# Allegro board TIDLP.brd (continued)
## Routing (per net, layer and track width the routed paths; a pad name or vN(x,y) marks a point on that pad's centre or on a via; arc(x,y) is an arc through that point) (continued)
UART1_DTR_CON: length 3.2
  TOP w0.178: R22.1 197.62,70.98 J21.4
UART1_RSTZ_CON: length 8.2
  TOP w0.178: U12.14 191.09,71.34 191.43,71.67 192.68,71.67 193.11,72.1 193.11,72.1 193.91,72.9 195.71,72.9 196.22,72.39 197.65,72.39 J21.8
UART1_RTSZ: length 121.1
  TOP w0.178: v1(136.68,72.47) 137.51,72.47 137.56,72.52 140.55,72.52 140.91,72.16 v1(141.59,72.16) ; U11.A19 v2(80.66,82.2) ; U12.11 189.14,69.01 v1(188.98,68.85)
  LY4 w0.102: 107.45,73.16 107.02,73.59 99.36,73.59 98.55,74.4 98.42,74.4 96.78,76.04 90,76.04 87.46,78.58 87.46,78.82 87.09,79.19 87.09,79.73 86.03,80.8 85.51,80.8 85.27,81.04 85.27,81.15 84.83,81.59 84.5,81.59 84.27,81.36 84.27,80.76 84.1,80.59 83.19,80.59 83.06,80.73 83.06,81.36 82.83,81.59 82.23,81.59 82.02,81.81 81.5,81.81 81.11,82.2 v2(80.66,82.2)
  LY4 w0.171: 107.45,73.16 111.26,73.16 111.49,72.93 114,72.93 114.23,73.16 117.44,73.16 118.47,72.13 132.56,72.13 133.36,72.92 135.63,72.92 136.08,72.47 v1(136.68,72.47) ; v1(188.98,68.85) 187.95,67.82 177.02,67.82 174.57,70.27 171.22,70.27 170.92,69.98 167.23,69.98 166.93,70.27 166.06,70.27 164.89,71.44 161.2,71.44 160.95,71.69 160.03,71.69 159.78,71.44 158.78,71.44 158.09,72.13 156.86,72.13 156.31,72.68 154.13,72.68 153.58,72.13 141.62,72.13 v1(141.59,72.16)
UART1_RXD: length 243.5
  TOP w0.178: U12.9 186.55,70.57 v1(185.82,69.84) ; v1(141.83,73.86) 137.98,73.86 137.93,73.91 137.4,73.91 137.2,73.7 v1(136.63,73.7) ; v1(114.99,110.07) 114.99,111.23 115.1,111.34 115.1,111.85 114.99,111.96 114.99,112.12 114.88,112.23 114.88,112.73 114.99,112.84 J3.92 ; U11.D19 v2(83.66,82.2)
  LY3 w0.171: v1(134.76,108.69) 129.76,108.69 v1(129.6,108.54) ; v1(189.19,107.49) 187.62,105.92 186.63,105.92 185.86,105.14 185.86,104.03 186.24,103.65 186.5,103.65 188.37,101.78 188.37,99.61 185.87,97.11 185.87,89.86 184.28,88.27 184.28,86.45 185.29,85.44 185.29,82.02 184.94,81.67 184.94,81.17 185.72,80.39 185.72,75.71 186.05,75.38 186.05,74.49 184.93,73.37 184.93,70.74 v1(185.82,69.84)
  LY4 w0.102: v2(83.66,82.2) 84.11,82.2 84.5,82.59 84.83,82.59 85.06,82.36 85.06,82 85.26,81.8 85.91,81.8 87.87,79.84 87.87,78.85 90.17,76.55 96.85,76.55 98.59,74.81 99.02,74.81 99.23,74.59 106.88,74.59 107.45,74.03
  LY4 w0.171: v1(141.83,73.86) 142.89,73.86 143.69,73.06 153.29,73.06 153.91,73.68 156.53,73.68 156.97,73.24 161.18,73.24 162.11,72.31 166,72.31 166.78,71.53 170.18,71.53 170.25,71.6 175.99,71.6 177.09,70.51 177.09,70.48 178.43,69.14 178.92,69.14 179.34,69.56 180.53,69.56 181.33,68.76 184.26,68.76 185.35,69.84 v1(185.82,69.84) ; v1(136.63,73.7) 136.57,73.63 133.06,73.63 132.49,73.06 119.51,73.06 118.55,74.03 114.09,74.03 113.7,73.65 111.78,73.65 111.4,74.03 107.45,74.03 ; v1(189.19,107.49) 187.75,108.93 178.53,108.93 176.75,107.15 175.87,107.15 173.74,105.02 173.03,104.31 173.03,104.31 172.03,103.31 166.8,103.31 165.95,104.16 165.1,104.16 165.02,104.08 163.6,104.08 163.14,103.62 156.24,103.62 155.21,104.65 138.73,104.65 134.76,108.62 v1(134.76,108.69)
  BOTTOM w0.178: v1(114.99,110.07) 115.89,110.07 116.84,109.12 118.14,109.12 118.35,108.91 126.21,108.91 126.84,108.28 128.22,108.28 128.29,108.21 129.27,108.21 v1(129.6,108.54)
UART1_RXD_CON: length 13
  TOP w0.178: v1(186.82,76.07) 187.24,76.49 U12.8 ; v1(195.14,73.98) 195.33,73.79 J21.3
  BOTTOM w0.178: v1(195.14,73.98) 195.14,73.98 193.62,75.5 187.39,75.5 v1(186.82,76.07)
UART1_TXD: length 273.1
  TOP w0.178: J3.53 100.49,120.98 100.55,121.05 100.55,121.93 100.49,122 v1(100.49,122.27) ; v1(142.26,80.65) 142.02,80.41 141.88,80.41 139.75,78.28 129.93,78.28 128.85,77.19 127.75,77.19 125.91,75.35 123.58,75.35 123.27,75.65 123.27,76.15 122.51,76.92 122.45,76.92 122.27,77.1 122.27,84.11 125.35,87.19 125.7,87.19 126.04,87.54 126.04,87.91 127.62,89.49 127.62,89.97 134.77,97.11 136.41,97.11 138.16,98.86 138.16,104.56 138.11,104.6 138.11,104.94 137.48,105.57 137.48,105.68 137.11,106.05 137,106.05 135.57,107.48 135.57,109.86 134.3,111.12 134.3,112.72 136.12,114.54 136.12,118.87 140.09,122.84 141.84,122.84 v1(146.49,127.5) ; v1(186.75,69.85) 187.15,69.85 187.53,69.47 188.16,69.47 188.36,69.67 188.36,70.44 U12.10 ; v1(137.67,73.27) 137.83,73.1 v1(140.87,73.1) ; U11.C19 v2(82.66,82.2)
  LY4 w0.102: v2(82.66,82.2) 83.27,81.59 84.21,81.59 84.42,81.8 84.91,81.8 85.11,81.59 85.83,81.59 86.06,81.36 86.06,81.35 86.23,81.18 86.23,80.98 87.66,79.55 87.66,78.77 90.12,76.31 96.8,76.31 98.51,74.6 98.77,74.6 99.57,73.8 107.12,73.8 107.33,73.6 107.63,73.6
  LY4 w0.171: v1(137.67,73.27) 137.46,73.06 136.94,73.06 136.93,73.07 135.99,73.07 135.78,73.28 133.21,73.28 132.54,72.61 118.83,72.61 117.84,73.6 114.16,73.6 113.85,73.29 111.64,73.29 111.33,73.6 107.63,73.6 ; v1(186.75,69.85) 185.15,68.25 177.73,68.25 175.28,70.7 171.04,70.7 170.74,70.41 167.41,70.41 167.11,70.7 166.26,70.7 166.26,70.7 166.24,70.7 165.07,71.87 161.38,71.87 161.13,72.12 160.55,72.12 160.07,72.61 156.99,72.61 156.43,73.17 154.01,73.17 153.45,72.61 141.99,72.61 141.84,72.76 141.22,72.76 v1(140.87,73.1)
  BOTTOM w0.178: v1(142.26,80.65) 142.28,80.64 142.28,77.87 v1(137.67,73.27) ; v1(100.49,122.27) 100.49,123.19 102.28,124.99 107.3,124.99 108.84,123.44 110.91,123.44 112.61,121.74 112.61,120.51 113.83,119.29 115.18,119.29 115.18,119.29 115.8,119.29 115.8,119.29 116.84,119.29 117.01,119.28 120.22,119.28 122.23,117.28 124.25,117.28 124.75,117.77 125.77,117.77 126.63,118.63 127.73,118.63 130.62,121.52 130.62,121.79 132.97,124.13 136.74,124.13 137.71,125.1 139.5,125.1 139.5,125.09 143.61,125.09 146.02,127.5 v1(146.49,127.5)
UART1_TXD_CON: length 11.4
  TOP w0.178: J21.2 197.55,76.45 194.25,76.45 193.71,75.92 193.24,75.92 192,74.68 189.09,74.68 188.49,75.27 U12.7
USB_DAT_N: length 14.5
  LY4 w0.105: J5.2 7.35,109.45 7.35,110.28 8.36,111.29 12.28,111.29 12.68,111.69 12.68,112.34 12.81,112.47 v1(14.51,112.47)
  BOTTOM w0.108: U503.4 13.53,112.47 v1(14.51,112.47) 14.51,112.77 14.88,113.14 16.25,113.14 16.51,112.88 R515.1
USB_DAT_NS: length 150.7
  TOP w0.178: U11.C5 v2(82.66,67.2)
  LY4 w0.102: v2(82.66,67.2) 82.66,67.04 82.85,66.85 83.06,66.85 83.14,66.94 83.14,67.46 83,67.6 81.51,67.6 81.27,67.36 81.27,65.96 80.91,65.6 80.15,65.6 79.82,65.27 79.82,64.68 78.8,63.66 78.76,63.66
  LY4 w0.105: v1(16.57,118.61) 16.58,118.61 16.93,118.25 16.93,115.18 16.03,114.28 16.03,111.08 8.02,103.06 8.02,87.18 8.58,86.62 8.58,86.11 9.22,85.47 9.22,71.1 15.05,65.26 24.57,65.26 32.75,57.07 45.27,57.07 46.57,55.77 57.29,55.77 58.37,54.69 61.54,54.69 63.06,56.21 63.76,56.21 65.8,58.25 72.96,58.25 76.16,61.46 76.16,62.2 77.62,63.66 78.76,63.66
  BOTTOM w0.108: v1(16.57,118.61) 16.14,119.03 12.86,119.03 12.65,118.82 12.65,118.21 12.89,118.11 DN504.1 13.88,118.11 15.1,116.89 R515.2
USB_DAT_P: length 15.5
  LY4 w0.105: J5.3 7.1,109.39 7.1,110.39 8.26,111.55 12.18,111.55 12.42,111.79 12.42,112.34 12.29,112.47 v1(10.59,112.47)
  BOTTOM w0.108: R516.1 v1(10.59,112.47) 11.62,112.47 U503.6 11.62,110.58 R539.1
USB_DAT_PS: length 150.7
  TOP w0.178: U11.D6 v2(83.66,68.2)
  LY4 w0.102: 78.76,63.91 78.76,63.91 79.61,64.76 79.61,65.35 80.07,65.81 80.83,65.81 81.06,66.04 81.06,66.06 81.07,66.07 81.07,67.45 81.42,67.81 83.27,67.81 v2(83.66,68.2)
  LY4 w0.105: v1(17.56,118.61) 17.19,118.23 17.19,115.07 16.29,114.17 16.29,110.97 8.27,102.95 8.27,87.29 8.83,86.73 8.83,86.21 9.47,85.57 9.47,71.2 15.16,65.51 24.67,65.51 32.86,57.33 45.37,57.33 46.68,56.02 57.4,56.02 58.47,54.95 61.44,54.95 62.95,56.46 63.65,56.46 65.7,58.5 72.85,58.5 75.91,61.56 75.91,62.31 77.51,63.91 78.76,63.91
  BOTTOM w0.108: R516.2 9.06,116.89 11.22,119.05 DN504.2 11.55,118.98 12.49,118.98 12.77,119.25 16.91,119.25 v1(17.56,118.61)
USB_ENZ: length 124.7
  TOP w0.178: U11.E25 v2(84.66,88.2)
  LY3 w0.171: v1(10.62,108.74) 12.52,108.74 16.04,105.23 18.88,105.23 19.43,105.78 21.04,105.78 21.86,104.96 21.86,103.98 19.09,101.21 19.09,97.1 14.77,92.79 v1(12.76,92.79)
  LY4 w0.102: v2(84.66,88.2) 84.51,88.2 84.06,88.65 84.06,89.36 83.83,89.59 83.82,89.59 83.76,89.66 83.33,89.66 82.82,90.17
  LY4 w0.171: 82.82,90.17 82.7,90.17 82.16,90.72 81.79,90.72 81.13,91.38 79.03,91.38 78.03,92.38 74.18,92.38 73.46,93.1 71.5,93.1 70.74,92.35 69.5,92.35 67.99,93.87 66.61,93.87 66.6,93.88 66.02,93.88 65.59,93.45 62.04,93.45 61.53,93.95 60.69,93.95 60.12,93.39 54.25,93.39 52.76,91.89 52.76,91.66 52.48,91.39 51.83,91.39 51.22,92 49.58,92 49.02,91.44 47.94,91.44 47.41,90.91 46.55,90.91 46.42,91.04 45.7,91.04 42.35,94.39 41.77,94.39 39.76,96.39 39.18,96.39 38.21,97.36 35.85,97.36 35.39,96.9 33.92,96.9 33.03,97.79 27.83,97.79 24.97,100.65 21.69,100.65 21.04,101.29 20.69,101.65 20.48,101.85 13.45,101.85 12.42,100.82 12.42,93.13 v1(12.76,92.79)
  BOTTOM w0.178: U504.1 12.71,108.72 R538.1 10.63,108.72 v1(10.62,108.74)
XCLKIN: length 5.3
  TOP w0.178: v1(41.46,105.86) 40.11,105.86 39.64,105.39 U7.90
  BOTTOM w0.178: R536.1 40.8,105.86 v1(41.46,105.86)
XCLKOUT: length 7.6
  TOP w0.178: U7.66 50.72,98.02 51.38,97.36 51.88,97.36 52.5,96.74 52.5,95.33 52.84,94.99 52.84,94.12 TP19.1
XTAL_IN: length 14.3
  TOP w0.178: U11.M26 v2(91.66,89.2)
  BOTTOM w0.102: 90.98,90.83 91.03,90.79 91.03,89.83 v2(91.66,89.2)
  BOTTOM w0.178: X500.1 87.07,99.49 90.94,95.62 C553.1 90.94,91.85 R580.1 90.98,91.77 90.98,90.84 90.98,90.83
XTAL_OUT: length 3.6
  TOP w0.178: U11.N26 v2(92.66,89.2)
  BOTTOM w0.102: 91.94,90.17 91.94,89.93 v2(92.66,89.2)
  BOTTOM w0.178: R580.2 91.94,91.8 R581.2 91.94,90.17
N16773791: length 3.1
  TOP w0.178: J3.1 87.49,123.13 R1.2
N16781966: length 4.3
  TOP w0.178: J2.92 63.87,113.05 63.58,112.76 63.58,112.36 R8.2 63.91,111.9 63.96,111.86 64.49,111.86 64.53,111.9 R9.2
N16826457: length 8
  TOP w0.178: Q4.3 177.29,43.74 178.5,43.74 179.45,42.78 179.45,42.69 179.46,42.68 179.46,42.15 179.45,42.15 v1(179.45,41.47)
  BOTTOM w0.178: v1(179.45,41.47) 179.45,39.19 R715.2
N16826574: length 11.4
  TOP w0.178: Q3.3 172.48,47.17 172.89,46.75 172.89,46.55 v1(173.24,46.19) 173.93,46.88 174.07,46.88 175.17,47.98 177.44,47.98 v1(177.47,48.01) Q4.2
  BOTTOM w0.178: v1(173.24,46.19) 173.2,46.24 R706.2
N16826732: length 61.2
  LY3 w0.171: v1(183.07,79.06) 178.99,74.99 178.99,71.76 178.81,71.58 178.81,70.71 178.08,69.98 178.08,68.97 179.26,67.78 179.26,67.02 179.9,66.38 179.9,65.61 182.45,63.06 182.45,51.24 175.61,44.4 175.61,33.13 171.56,29.09 v1(171.56,28.4)
  BOTTOM w0.178: v1(183.07,79.06) Q503.3 ; R726.1 v1(171.56,28.4)
N16826745: length 7.2
  TOP w0.178: v1(168.77,47.74) 168.77,48.36 168.32,48.81 168.32,49.34 169.35,50.37 171.05,50.37 Q3.2
  BOTTOM w0.178: R707.2 v1(168.77,47.74)
N16826772: length 12.7
  TOP w0.178: J22.1 187.28,60.62 v1(181.74,66.17)
  BOTTOM w0.178: R630.2 v1(181.74,66.17)
N16826808: length 13.3
  TOP w0.178: R37.1 174.41,34.29 173.6,33.47 v1(173.6,29.21) ; v1(173.6,29.21) 172.54,29.21 171.03,30.72 Q5.1 ; v1(173.6,29.21) 175.39,29.21 C32.2
  BOTTOM w0.178: R726.2 v1(173.6,29.21)
N16827011: length 12.1
  BOTTOM w0.178: R581.1 92.98,92.3 C554.1 92.32,95.36 96.57,99.62 X500.2
N16827097: length 6.5
  BOTTOM w0.178: R599.2 184.68,78.12 Q503.2
N16827292: length 4
  TOP w0.178: U15.1 164.34,57.53 165.99,55.87 v1(165.99,55.87)
  BOTTOM w0.178: R668.1 165.99,55.87 v1(165.99,55.87)
N16827323: length 2.4
  TOP w0.178: U17.4 181.28,31.79 R38.2 R52.1
N16827429: length 6.8
  TOP w0.178: D9.2 177.79,42.42 v1(178.82,42.42)
  BOTTOM w0.178: R714.2 175.54,39.33 176.21,39.33 176.99,40.11 176.99,40.59 v1(178.82,42.42)
N16827460: length 2.1
  TOP w0.178: R39.2 184.54,32.79 184.11,32.36 U17.1
N16827499: length 5.7
  TOP w0.178: D9.3 174.63,41.13 v1(174.22,41.55)
  BOTTOM w0.178: v1(174.22,41.55) 172.84,40.17 172.31,40.17 171.4,39.25 R716.2
N16827743: length 3
  TOP w0.178: R40.2 186.57,33.01 186.57,31.99 186.04,31.46 D10.2
N16827874: length 2.5
  TOP w0.178: D9.4 177.77,41.13 v1(177.77,39.94)
  BOTTOM w0.178: R715.1 177.77,38.79 v1(177.77,39.94)
N16830133: length 17.9
  BOTTOM w0.178: R685.1 R684.1 134.04,56.29 v1(136.66,56.29) ; U512.1 136.91,55.45 136.69,55.68 136.69,56.26 v1(136.66,56.29) ; v1(136.66,56.29) 137.13,56.75 U512.3 138.51,56.77 139.38,56.77 139.95,57.34 139.95,59.09 140.23,59.37 140.23,59.55 140.61,59.92 141.14,59.92 141.52,59.55 141.52,59.01 141.45,58.95 141.45,58.63 142.68,57.4 U512.11
N16830205: length 35.2
  TOP w0.178: U15.30 153.86,61.08 v1(153.86,61.09)
  LY4 w0.171: v1(153.86,61.09) 153.82,61.05 v1(151.68,61.05) 151.2,60.58 149.22,60.58 148.46,59.81 148.46,58.82 147.93,58.3 145.32,58.3 143.04,60.58 141.09,60.58 139.9,59.4 138.12,59.4 v1(135.78,57.05)
  BOTTOM w0.178: R678.1 149.36,57.53 R679.2 149.58,58 149.58,58.31 149.6,58.33 149.6,58.42 149.96,58.78 149.96,59.6 v1(149.57,59.99) 150.16,60.58 151.21,60.58 v1(151.68,61.05) ; U512.4 136.13,57.4 v1(135.78,57.05) 135.29,57.53 C667.1
N16830232: length 3
  BOTTOM w0.178: R634.1 150.06,62.2 150.67,61.59 150.88,61.59 v1(150.98,61.7)
  vias: v1(146.59,59.92) v1(148.29,61.58) v1(148.35,60.67) v1(149.22,61.21) v1(151.87,61.98)
N16830236: length 6.2
  TOP w0.178: L5.2 132.73,64.64 D5.2
N16830344: length 29.9
  LY3 w0.171: v1(146.94,59.05) 146.94,55.12 149.14,52.92 151.2,52.92 v1(151.21,52.91) 151.73,52.38 v1(151.73,47.75)
  BOTTOM w0.178: R677.2 151.39,53.1 v1(151.21,52.91) ; R717.2 147.24,44.5 C676.2 147.32,46.84 148.23,47.75 Q505.3 v1(151.73,47.75) 151.92,47.93 C675.2 ; R680.2 146.89,59 v1(146.94,59.05)
N16830356: length 5
  BOTTOM w0.178: R639.1 135.37,65.43 136.51,64.29 U510.6
N16830372: length 2.7
  TOP w0.178: D5.1 R25.1
N16830397: length 4.9
  BOTTOM w0.178: U510.5 135.84,63.64 134.99,64.49 133.86,64.49 R640.2
N16830529: length 9.6
  BOTTOM w0.178: 137.05,61.69 U510.2 ; 137.05,61.69 135.12,61.69 ; 137.05,61.69 137.05,61.26 137.27,61.04 U510.1 ; 137.05,61.69 137.05,62.23 137.2,62.38 138.33,62.38 U510.3 ; 135.12,61.69 134.56,62.26 R637.1 ; 135.12,61.69 134.67,61.24 R638.1
N16830564: length 4.8
  BOTTOM w0.178: R682.1 134.29,59.33 136.16,59.33 136.79,58.7 U512.6
N16830576: length 36.3
  TOP w0.254: U15.32 154.21,60.08 154.19,60.1 153,60.1 152.58,59.68 v1(150.84,59.68)
  LY4 w0.171: v1(150.84,59.68) 149.51,58.36 ; 149.51,58.36 148.03,56.88 144.06,56.88 141.65,59.28 v1(140.87,59.28) ; 149.51,58.36 150.03,57.85 150.03,52.18 150.89,51.32 v1(153.64,51.32)
  BOTTOM w0.178: C675.1 v1(153.64,51.32) R670.2 R677.1 ; U512.14 143.21,55.45 142.86,55.81 142.86,56.49 140.66,58.69 140.66,59.06 v1(140.87,59.28)
N16830606: length 12
  TOP w0.178: U15.33 154.57,59.58 154.55,59.56 154,59.56 153.97,59.59 153.25,59.59 152.65,58.99 152.65,55.82 152.26,55.42 151.69,55.42 151.3,55.03 151.3,54.52 151.07,54.29 151.07,54.1 v1(150.76,53.8)
  BOTTOM w0.178: Q505.1 149.67,52.32 150.47,53.12 150.47,53.5 150.52,53.55 150.52,53.56 v1(150.76,53.8)
N16830689: length 1.8
  BOTTOM w0.178: R680.1 145.83,56.75 U512.12
N16830707: length 1.9
  BOTTOM w0.178: U512.13 145.62,56.1 R681.2
N16830891: length 4.7
  BOTTOM w0.178: R683.2 134.09,58.65 135.72,58.65 136.32,58.05 U512.5
N16836092: length 15.9
  TOP w0.178: J64.1 v1(142.22,1.91)
  BOTTOM w0.178: v1(142.22,1.91) 142.22,4.04 C702.2
  BOTTOM w1.27: R779.2 C702.2 R761.1 142.24,8.64 143.82,10.22 L506.1
N16836211: length 11.4
  TOP w0.178: VR2.2 116.62,12.32 115.1,10.79 TP70.1
  BOTTOM w0.178: TP70.1 113.15,9.65 110.88,9.65 R763.2 110.76,8.79 111.04,8.51 111.04,6.94 110.89,6.79 U521.3
N16862598: length 3.9
  TOP w0.178: J53.3 15.87,2.64 15.18,1.96 v1(15.18,1.91)
  BOTTOM w0.178: R786.2 14.99,2.1 v1(15.18,1.91) 15.3,1.91 15.88,2.48 R785.2
N16862628: length 2
  BOTTOM w0.178: Q504.2 122.43,55.4 R687.1
N16862652: length 1.7
  BOTTOM w0.178: R643.2 121.41,63.53 U511.4
N16862691: length 1.6
  BOTTOM w0.178: U526.4 13.34,5.31 R787.2
N16862716: length 5.3
  BOTTOM w0.178: U526.5 11.16,5.6 10.73,5.6 10.3,6.03 R775.2 ; U526.5 11.38,6.41 10.73,7.05 10.36,7.05 R774.2 ; U526.5 11.38,5.09 11.24,4.95 10.43,4.95 C709.2
N16862889: length 3.8
  BOTTOM w0.178: C644.2 R641.2 R642.2 123.44,63.53 U511.5
N16862891: length 1.3
  BOTTOM w0.178: Q504.3 R686.2
N16869658: length 82.8
  TOP w0.178: v1(31.81,114.58) 31.81,106.94 32.33,106.42 33.07,106.42 33.97,107.31 J6.1 ; v1(31.81,119.61) 35.4,123.2 35.4,124.26 36.58,125.45 74.74,125.45 76.7,123.49 79.77,123.49 82.21,121.05 82.21,118.31 82.03,118.14 82.03,116.3 82.02,116.28 82.03,116.01 82.03,115.58 82.65,114.95 82.65,112.88 82.41,112.64 R530.2 82.06,112.62 U4.1
  LY3 w0.171: v1(31.81,114.58) v1(31.81,119.61)
N16869662: length 5.5
  TOP w0.178: U4.55 81.56,104.77 81.76,104.97 v1(81.76,105) ; v1(81.76,105) 82.95,106.18 R548.2 ; v1(81.76,105) 82.06,104.7 U4.56
N16888382: length 12
  TOP w0.178: J52.8 196.7,14.94 197.61,15.85 197.61,18.64 196.7,19.56 v1(195.05,19.56) 194.18,18.69 J52.1
  BOTTOM w0.178: R753.1 195.02,19.58 v1(195.05,19.56)
N16888389: length 5.9
  TOP w0.178: J52.13 193.16,12.44 192.91,12.18 192.91,11.21 v1(194.56,9.55)
  BOTTOM w0.178: R737.1 194.58,9.57 v1(194.56,9.55)
N16888395: length 4.3
  TOP w0.178: J52.11 196.07,13.44 196.15,13.36 v1(196.15,13.19)
  BOTTOM w0.178: R739.1 195.68,13.7 195.81,13.7 196.15,13.36 v1(196.15,13.19)
N16888418: length 4.7
  TOP w0.178: J52.12 195.52,12.94 195.66,12.79 195.68,12.79 196.2,12.27 v1(196.57,12.27)
  BOTTOM w0.178: v1(196.57,12.27) 196.42,12.12 R738.1
N16902445: length 192.5
  TOP w0.178: J9.5 v1(60.61,108.56)
  LY3 w0.171: v1(81.83,129.1) 81.83,129.24 83.28,130.68 84.76,130.68 84.86,130.79 86.58,130.79 86.6,130.77 87.39,130.77 87.41,130.79 89.12,130.79 89.14,130.77 89.93,130.77 89.95,130.79 91.66,130.79 91.68,130.77 92.47,130.77 92.49,130.79 94.2,130.79 94.22,130.77 95.01,130.77 95.03,130.79 96.74,130.79 96.76,130.77 97.55,130.77 97.57,130.79 99.28,130.79 99.3,130.77 100.09,130.77 100.11,130.79 104.36,130.79 104.38,130.77 105.17,130.77 105.19,130.79 106.9,130.79 106.92,130.77 107.71,130.77 107.73,130.79 108.95,130.79 109.05,130.68 118.91,130.68 128.84,120.75 128.84,112.97 128.23,112.36 127.4,112.36 127.16,112.6 126.67,112.6 126.23,112.16 126.23,108.18 127.21,107.19 v1(127.77,107.19) ; v1(59.3,115.75) 60.61,114.43 v1(60.61,108.56)
  LY4 w0.171: v1(59.3,115.75) 59.3,118.49 66.28,125.48 75.44,125.48 79.06,129.1 v1(81.83,129.1) ; v1(127.77,107.19) 127.77,97.16 127.27,96.65 127.27,96.12 128.59,94.8 128.59,91.73 129.23,91.09 129.23,91.08 129.58,90.73 129.59,90.73 131.42,88.9 131.42,87.2 128.23,84.02 128.23,83.56 126.15,81.48 126.15,79.27 129.66,75.77 137.66,75.77 138.9,74.53 138.9,72.14 138.05,71.28 137.56,71.28 137.39,71.45 136.1,71.45 135.34,72.21 133.65,72.21 132.63,71.2 130.86,71.2 128.57,68.91 128.57,68.65 128.21,68.28 126.08,68.28 125.79,68.57 125,68.57 124.72,68.28 122.18,68.28 121.29,67.39 119.94,67.39 119.59,67.74 112.56,67.74 112.38,67.92 111.22,67.92 110.91,68.23 110.91,69.39 110.15,70.15 v1(110.06,70.15)
  BOTTOM w0.178: R649.1 R626.1 v1(110.06,70.15)
N16906032: length 3.4
  TOP w0.178: U12.2 191.74,79.58 C21.1
N16906053: length 4
  TOP w0.178: C20.1 188.27,78.97 188.27,78.28 189.14,77.41 U12.6
N16906057: length 3.5
  TOP w0.178: U12.1 193.02,76.49 v1(193.36,76.83)
  BOTTOM w0.178: C577.2 193.17,76.64 v1(193.36,76.83)
N16906061: length 4.2
  TOP w0.178: U12.3 v1(191.09,78)
  BOTTOM w0.178: v1(191.09,78) 190.85,77.76 190.07,77.76 189.09,76.78 C577.1
N16906093: length 3.8
  TOP w0.178: U12.4 190.44,77.91 190.21,78.14 v1(190.21,78.48)
  BOTTOM w0.178: C576.2 190.21,79.08 v1(190.21,78.48)
N16906098: length 3.7
  TOP w0.178: U12.5 189.79,77.54 189.09,78.24 v1(189.09,78.56)
  BOTTOM w0.178: C576.1 v1(189.09,78.56)
N16906262: length 77.2
  TOP w0.178: v1(139.44,81.56) 139.44,81.56 U10.8 136.17,83.47 135.8,83.84 133.11,83.84 131.72,82.45 U9.8 ; U6.16 v1(192.01,101.55)
  LY4 w0.171: v1(139.44,81.56) 145.07,81.56 148.94,85.43 150.81,85.43 152.6,87.21 165.96,87.21 166.52,87.78 170.24,87.78 178.62,96.15 182.11,96.15 185.08,99.13 185.08,100.31 187.35,102.58 191.03,102.58 192.01,101.6 v1(192.01,101.55)
  BOTTOM w0.178: R541.1 R540.1 192.01,102.49 v1(192.01,101.55)
N16906499: length 3.4
  TOP w0.178: U6.2 191.36,112.09 C8.1
N16906505: length 8.6
  BOTTOM w0.178: R537.2 13.74,108.69 U504.2 13.72,108.01 13.09,107.39 12.46,107.39 11.11,106.05 J5.1
N16906696: length 3.3
  TOP w0.178: C7.1 188.76,112.28 U6.6
N16906819: length 2.6
  TOP w0.178: U6.1 192.1,109.09 v1(193.42,109.09)
  BOTTOM w0.178: C515.2 v1(193.42,109.09)
N16906911: length 3
  TOP w0.178: v1(190.3,107.61) 190.71,108.03 U6.3
  BOTTOM w0.178: C515.1 v1(190.3,107.61)
N16906913: length 14.3
  BOTTOM w0.178: U504.4 15.23,106.22 16.34,107.33 16.34,111.01 16.14,111.21 12.97,111.21 12.63,110.87 12.63,109.99 12.21,109.57 10.29,109.57 10.11,109.75 10.11,110.18 R539.2
N16907106: length 3.7
  TOP w0.178: U6.4 190.06,110.48 v1(190.42,110.84)
  BOTTOM w0.178: C507.2 190.7,111.12 v1(190.42,110.84)
N16907207: length 3.7
  TOP w0.178: U6.5 v1(189.41,110.83)
  BOTTOM w0.178: v1(189.41,110.83) 188.77,111.47 C507.1
N16910878: length 4.4
  TOP w0.254: v1(48.86,79.82) 49.55,79.82 49.99,79.39 49.99,79.17 50,79.17 U14.53
  BOTTOM w0.254: R610.2 50.04,79.34 49.91,79.47 49.55,79.82 v1(48.86,79.82)
N16910921: length 4
  TOP w0.178: v1(55.82,57.28) 56,57.45 U14.16
  BOTTOM w0.178: R698.1 R699.2 56,56.35 56,57.19 55.91,57.28 v1(55.82,57.28)
N16911179: length 3.3
  TOP w0.254: v1(62.5,79.91) 62.5,79.79 61.99,79.29 U14.29
  BOTTOM w0.254: R608.2 61.99,79.03 61.99,79.29 62.5,79.79 v1(62.5,79.91)
N16911537: length 4.4
  TOP w0.178: U14.27 61.49,59.94 61.73,60.17 62.36,60.17 62.8,59.74 v1(62.8,59.35)
  BOTTOM w0.178: R696.2 62.77,59.32 v1(62.8,59.35)
N16912987: length 8.6
  TOP w0.178: v1(57.07,53.19) 56.48,53.77 56.48,56.72 56.64,56.87 56.64,57.4 56.49,57.55 U14.17
  BOTTOM w0.178: v1(57.07,53.19) 57.29,53.41 57.6,53.41 58.14,53.94 R697.2
N16969756: length 316.5
  TOP w0.178: v1(187.07,8.83) 187.2,8.7 R66.2
  LY3 w0.171: v1(31.72,9.23) 31.22,9.73 30.75,9.73 30.59,9.88 30.1,9.88 29.94,9.73 28.59,9.73 26.77,11.55 20.8,11.55 19.05,13.31 19.05,29.08 19.05,29.09 19.05,30.56 24.08,35.6 24.08,43.73 19.98,47.82 19.98,62.15 21.54,63.71 21.54,64.98 23.19,66.63 23.19,72.17 23.18,72.17 22.83,72.52 22.83,73.02 23.18,73.37 23.19,73.37 23.19,75.14 26.52,78.47 26.52,81.22 26.27,81.46 26.27,83.3 25.44,84.13 25.44,85.04 23.69,86.79 23.69,100.51 22.82,101.37 22.82,102.87 23.46,103.5 23.46,105.26 21.78,106.93 19.01,106.93 18.12,107.83 18.12,118.32 18.16,118.36 18.16,120.48 15.27,123.37 v1(13.11,123.37)
  LY4 w0.171: v1(31.72,9.23) 34.11,6.83 44,6.83 44.96,7.8 50.34,7.8 52.88,10.34 57.25,10.34 58.29,9.31 60.79,9.31 61.26,9.78 74.54,9.78 76.03,11.28 78.57,11.28 81.44,8.4 85.59,8.4 85.6,8.4 91.3,8.4 91.94,7.75 92.53,7.16 99.49,7.16 100.46,6.2 106.1,6.2 106.66,6.76 112.17,6.76 113.43,5.5 113.43,5.35 113.99,4.79 116.26,4.79 118.24,6.76 121.35,6.76 122.65,8.06 142.48,8.06 144.97,5.58 149.07,5.58 149.7,4.95 179.6,4.95 180.14,4.4 181.12,4.4 181.5,4.78 181.5,5.89 180.74,6.64 180.74,7.48 181.39,8.13 186.37,8.13 v1(187.07,8.83)
  BOTTOM w0.178: v1(13.11,123.37) 12.28,123.37 11.29,124.36 R506.1 ; R507.1 11.3,125.62 R506.1 ; R506.1 11.28,125.62 R508.2
N16969826: length 306.4
  LY3 w0.171: v1(30.34,9.29) 28.38,9.29 26.47,11.2 20.66,11.2 18.69,13.16 18.69,28.93 18.69,28.94 18.69,30.71 23.71,35.73 23.71,42.79 19.55,46.96 19.55,62.22 21.18,63.86 21.18,65.13 22.83,66.78 22.83,72.02 22.48,72.38 22.48,73.17 22.83,73.52 22.83,75.29 23.04,75.5 25.08,77.54 25.08,84.9 23.2,86.78 23.2,100.13 22.26,101.07 22.26,105.33 21.13,106.47 v1(18.33,106.47)
  LY4 w0.171: v1(30.34,9.29) 33.15,6.48 44.15,6.48 45.11,7.44 52.53,7.44 53.33,6.64 62,6.64 64.78,9.42 72.03,9.42 72.98,8.47 73.73,8.47 76.18,10.92 78.42,10.92 81.29,8.05 85.44,8.05 85.45,8.04 91.15,8.04 91.69,7.5 92.38,6.81 99.34,6.81 100.31,5.84 105.58,5.84 107.73,3.69 115.94,3.69 118.65,6.41 121.5,6.41 122.8,7.71 142.22,7.71 144.79,5.14 146.83,5.14 148.51,3.47 158.87,3.47 159.92,4.52 179.42,4.52 179.97,3.97 181.29,3.97 182.26,4.93 182.26,6.86 181.63,7.49 v1(181.63,7.49)
  BOTTOM w0.178: v1(18.33,106.47) 18.33,117.77 18.51,117.95 18.51,119 17.85,119.67 17.85,122.8 17.41,123.24 U500.1 ; v1(181.63,7.49) 181.96,7.82 181.96,8.1 182.29,8.43 U520.1 183.39,8.38 R756.1
N16973926: length 13.7
  TOP w0.178: U5.8 182.71,105.13 v1(182.71,103.63) ; U5.5 v1(180.39,109.7)
  LY3 w0.171: v1(180.39,109.7) 180.97,109.12 181.82,109.12 182.71,108.22 182.71,107.51 182.71,107.5 v1(182.71,103.63)
  BOTTOM w0.178: 182.83,104.7 C517.2 C518.2 ; 182.83,104.7 182.71,104.58 v1(182.71,103.63) ; 182.83,104.7 R517.2
N16985744: length 61.9
  TOP w0.178: v1(165.61,110.1) 165.61,110.22 165.61,110.23 U2.1
  LY3 w0.171: v1(174.32,57.53) 174.32,58.72 173.02,60.02 172.55,60.02 172.2,60.37 172.2,60.84 171.45,61.59 171.45,79.43 169.19,81.68 169.19,83.25 167.05,85.4 167.05,91.04 168.1,92.09 168.1,101.82 166.1,103.83 166.1,106.23 165.4,106.92 165.4,109.39 165.61,109.59 v1(165.61,110.1)
  BOTTOM w0.178: R666.1 v1(174.32,57.53)
N17028370: length 3.1
  TOP w0.178: R45.1 28.77,25.26 28.15,25.26 27.97,25.43 v1(27.95,25.43)
  BOTTOM w0.178: U517.23 26.91,25.4 26.95,25.44 27.48,25.44 27.49,25.43 v1(27.95,25.43)
N17028379: length 2.5
  TOP w0.178: R41.1 26.86,24.75 27.16,24.75 v1(27.21,24.8)
  BOTTOM w0.178: U517.22 27.16,24.75 v1(27.21,24.8)
N17028388: length 3.3
  TOP w0.178: R46.1 28.24,24.24 v1(28.05,24.43)
  BOTTOM w0.178: U517.21 26.95,24.1 26.99,24.15 27.76,24.15 v1(28.05,24.43)
N17028397: length 2.5
  TOP w0.178: v1(27.26,23.5) 26.87,23.11 R42.1
  BOTTOM w0.178: v1(27.26,23.5) 27.21,23.45 U517.20
N17028406: length 3.3
  TOP w0.178: R47.1 28.24,22.76 v1(28.22,22.78)
  BOTTOM w0.178: v1(28.22,22.78) 28.21,22.78 28.19,22.8 27.55,22.8 27.52,22.83 26.99,22.83 26.96,22.8 U517.19
N17028415: length 2.5
  TOP w0.178: v1(27.25,22.19) 26.46,22.19 R43.1
  BOTTOM w0.178: U517.18 27.17,22.15 27.27,22.25 27.27,22.19 v1(27.25,22.19)
N17028424: length 3.2
  TOP w0.178: v1(27.57,21.33) 26.74,21.33 R44.1
  BOTTOM w0.178: U517.17 27.4,21.5 v1(27.57,21.33)
N17028433: length 3.1
  TOP w0.178: R55.1 27.85,20.45 27.57,20.17 27.57,20.31 v1(27.43,20.31)
  BOTTOM w0.178: v1(27.43,20.31) 27.53,20.31 26.99,20.85 U517.16
N17028442: length 4.2
  TOP w0.178: v1(27.98,19.55) 27.86,19.55 27.84,19.53 27.31,19.53 27.29,19.55 26.63,19.55 R54.1
  BOTTOM w0.178: v1(27.98,19.55) 27.86,19.55 27.84,19.53 27.31,19.53 26.93,19.9 26.93,19.91 26.79,20.05 26.79,20.11 26.7,20.2 U517.15
N17028451: length 3.2
  TOP w0.178: R56.1 33.25,19.27 v1(33.25,19.23)
  BOTTOM w0.178: v1(33.25,19.23) 32.93,19.55 U517.11
N17031378: length 19
  TOP w0.178: v1(155.4,9.73) 154.28,8.62 J65.1
  BOTTOM w1.27: R778.2 C701.2 R760.1 154.31,8.64 v1(155.4,9.73) 155.88,10.22 L505.1
N17031778: length 19.3
  TOP w0.178: J66.1 165.71,7.98 v1(167.47,9.73)
  BOTTOM w1.27: L504.1 167.95,10.22 v1(167.47,9.73) 166.37,8.64 R759.1 C700.2 R777.2
N17032456: length 13.3
  TOP w0.635: J42.1 v1(142.07,23.7)
  BOTTOM w1.27: L503.1 142.55,24.19 v1(142.07,23.7) 140.97,22.61 R732.1 C691.2 R744.2
N17032580: length 13.3
  TOP w0.635: J43.1 v1(155.4,23.7)
  BOTTOM w1.27: L502.1 155.88,24.19 v1(155.4,23.7) 154.31,22.61 R731.1 C690.2 R743.2
N17032754: length 13.3
  TOP w0.635: J44.1 v1(167.47,23.7)
  BOTTOM w1.27: R742.2 C689.2 R730.1 166.37,22.61 v1(167.47,23.7) 167.95,24.19 L501.1
N17036356: length 19.4
  TOP w0.178: VR1.2 99.02,13.46 TP67.1
  BOTTOM w0.178: R765.2 106.93,7.69 105.38,6.14 U521.5 102.1,6.14 101.96,6.27 101.09,6.27 100.97,6.15 100.44,6.15 100.06,6.53 100.06,7.06 100.24,7.24 100.24,8.94 100.97,9.67 TP67.1
N17038227: length 4.8
  TOP w0.178: J57.2 66.04,5.52 66.23,5.71 v1(67.31,5.71)
  BOTTOM w0.178: R768.1 66.07,5.71 v1(67.31,5.71)
N17038557: length 3.6
  TOP w0.178: v1(76.81,5.12) 76.81,3.41 J58.2
  BOTTOM w0.178: R782.1 v1(76.81,5.12)
N17038579: length 1.8
  BOTTOM w0.178: R782.2 75.11,3.33 U522.4
N17059521: length 12.6
  BOTTOM w0.178: U501.11 174.94,117.36 174.29,118.01 U501.3 174.29,121.08 174.09,121.28 173.64,121.28 ; R511.1 172.11,119.49 172.63,120.02 U501.1 172.99,121.11 173.17,121.28 173.64,121.28 ; 173.64,121.28 U501.2
N17059557: length 75.6
  TOP w0.178: U2.30 155.52,113.79 v1(155.27,114.05)
  BOTTOM w0.178: R523.1 150.63,110.24 R524.2 150.51,110.36 154.19,114.05 v1(155.27,114.05) 156.12,114.9 156.12,121.82 157.92,123.62 157.92,127.54 157.36,128.09 157.27,128.09 156.89,128.47 156.89,129 156.99,129.1 156.99,129.13 158.9,131.04 178.66,131.04 181.08,128.63 181.08,124.84 180.21,123.97 180.21,120.76 180.74,120.23 182.7,120.23 183.35,119.58 183.35,118.3 182.28,117.22 179.54,117.22 C510.1 175.7,118.11 174.94,118.87 U501.4
N17059583: length 8.1
  TOP w0.178: L1.2 139.64,116.84 v1(139.64,112.9)
  BOTTOM w0.178: D500.2 138.9,112.16 v1(139.64,112.9)
N17059602: length 3.1
  BOTTOM w0.178: R525.1 144.69,109.09 D500.1
N17059826: length 2
  BOTTOM w0.178: R510.2 175.59,122.02 U501.5
N17060167: length 4.3
  BOTTOM w0.178: R509.1 178.33,119.51 177.45,118.63 176.56,118.63 176.24,118.95 U501.6
N17126992: length 9.1
  TOP w0.178: U11.AC10 v2(103.66,72.2)
  BOTTOM w0.102: 107.63,71.99 107.58,71.99 106.97,72.59 104.06,72.59 v2(103.66,72.2)
  BOTTOM w0.178: R623.2 110.39,71.99 107.63,71.99
N17126998: length 5.8
  TOP w0.178: U11.AF10 v2(106.66,72.2)
  BOTTOM w0.102: v2(106.66,72.2) 107.35,71.51 107.63,71.51
  BOTTOM w0.178: R624.2 111,71.58 110.91,71.58 110.82,71.5 107.64,71.5 107.63,71.51
N17133391: length 6.2
  TOP w0.178: J11.1 15.5,94.66 v1(15.13,94.28)
  BOTTOM w0.178: v1(15.13,94.28) C565.1 17.14,92.51 FB504.1
N17140999: length 1
  BOTTOM w0.178: R565.2 C524.1
N17141409: length 4.5
  BOTTOM w0.178: C514.1 35.45,114.11 FB500.1 37.11,115.44 37.87,114.68 38.23,114.68
N17141519: length 5
  BOTTOM w0.178: R536.2 38.66,109.17 U502.3
N17172867: length 7.8
  TOP w0.178: U11.AD10 v2(104.66,72.2)
  BOTTOM w0.102: v2(104.66,72.2) 105.16,71.7 106.85,71.7 107.5,71.05 107.63,71.05
  BOTTOM w0.178: 107.63,71.05 107.69,70.99 R625.2
N17173381: length 25.5
  BOTTOM w0.178: R709.1 121.02,47.89 121.5,47.4 127.28,47.4 127.32,47.37 129.1,47.37 129.73,48.01 131.89,48.01 133.35,46.55 TP46.1 132.08,43.31 130.62,43.31 129.35,44.58 C677.2 128.91,44.15 R720.2 129.74,41.98 U515.3
N17173524: length 15
  BOTTOM w0.178: R708.1 R709.2 121.3,49.4 120.33,49.4 119.95,49.02 119.95,47.75 120.84,46.86 126.57,46.86 127.77,45.66 127.77,44.74 C678.2
N17223452: length 26.7
  TOP w0.178: v1(98.75,97.82) 98.75,97.39 97.93,96.57 95.67,96.57 v1(95.12,97.12) 94.83,97.41 v1(86.87,97.41)
  BOTTOM w0.178: R526.2 99.72,96.3 99.72,97.13 100.35,97.76 101.51,97.76 102.11,97.16 C16.1 ; R526.2 C521.1 ; R526.2 99.4,95.99 FB7.1 98.3,96.94 98.75,97.39 v1(98.75,97.82) ; FB5.1 FB4.1 v1(86.87,97.41) ; FB6.1 95,97.12 v1(95.12,97.12)
N17234365: length 21.6
  TOP w0.178: v1(85.47,97.35) 86.97,98.84 95.65,98.84 v1(97.1,97.39)
  BOTTOM w0.178: C15.1 82.69,93.8 R527.2 C522.1 82.72,95.99 FB1.1 FB2.1 v1(85.47,97.35) ; v1(97.1,97.39) 97.02,97.31 97.02,96.46 96.77,96.22 FB3.1
N17320383: length 10.4
  TOP w0.178: TP25.1 33.97,80.7 32.15,82.52 32.15,84.01 33.13,84.99 33.69,84.99 34.76,86.06 34.76,87.32 35.14,87.69 U7.27
N17320387: length 6.3
  TOP w0.178: TP24.1 35.64,85.3 U7.28
N17320392: length 5.7
  TOP w0.178: TP26.1 36.83,86.75 36.14,87.44 U7.29
N17373497: length 34.2
  LY3 w0.171: v1(173.96,116.6) 173.96,106.21 170.95,103.2 170.95,90.09 v1(169.86,89)
  BOTTOM w0.178: R513.1 173.11,117.45 v1(173.96,116.6) ; v1(169.86,89) 170.8,89 R575.1 R588.1
N17385870: length 10.3
  TOP w0.178: U11.AB11 v2(102.66,73.2)
  BOTTOM w0.102: v2(102.66,73.2) 103.11,73.2 103.51,72.8 107.16,72.8 107.53,72.43 107.63,72.43
  BOTTOM w0.178: 107.63,72.43 109.95,72.43 110.71,73.2 110.71,73.29 110.91,73.49 111,73.49 R622.2
N17410797: length 15.7
  BOTTOM w0.508: R576.2 148.51,97.21 C529.2 148.59,99.5 149.55,100.46 Q500.3 152.32,100.46 152.94,101.07 152.94,103.62 152.35,104.21 152.35,105.35 152.8,105.8 R522.2
N17410821: length 12.2
  TOP w0.178: U2.33 155.52,112.29 155.23,112.58 154.39,112.58 153.91,112.11 v1(153.91,112.13)
  BOTTOM w0.178: v1(153.91,112.13) 152.1,110.31 152.1,106.21 150.92,105.03 Q500.1
N17410829: length 15.7
  TOP w0.178: U2.32 155.85,112.79 155.34,113.3 v1(154.74,113.3)
  LY3 w0.171: v1(154.74,113.3) 153.44,113.3 153.03,112.89 153.03,112.06 153.65,111.45 153.65,108.85 154.26,108.24 154.26,107.71 154.77,107.2 154.77,106.7 154.18,106.11 v1(154.18,103.94)
  BOTTOM w0.178: v1(154.18,103.94) R521.2 R522.1
N17418050: length 2.4
  BOTTOM w0.178: R749.1 43.63,15.55 U518.12
N17418052: length 2.4
  BOTTOM w0.178: U518.9 43.71,13.6 R750.1
N17418070: length 2.2
  BOTTOM w0.178: R746.1 53.33,13.72 52.8,14.25 U518.7
N17418072: length 1.9
  BOTTOM w0.178: R748.1 53.64,16.2 U518.4
N17418086: length 24.2
  BOTTOM w0.178: J46.3 27.97,15.4 27.97,12.63 26.87,11.54 20.88,11.54 20.22,12.19 U525.2 13.21,12.19 13.09,12.08 12.56,12.08 12.43,12.2 U519.22
N17418489: length 7
  BOTTOM w0.178: R747.1 51.87,18.16 U518.1 51.09,18.15 50.57,18.67 49.28,18.67 J48.1
N17423586: length 11.5
  BOTTOM w0.178: J46.1 24.8,12.1 21.54,12.1 20.49,13.14 U525.4 16.68,14.26 R751.1
N17451899: length 6.2
  TOP w0.178: SW1.1 66.56,15.19 69.94,15.19 70.18,14.95 v1(70.18,13.46)
  BOTTOM w0.178: R710.2 v1(70.18,13.46)
N17529082: length 1.7
  BOTTOM w0.178: R776.2 173.41,3.98 Q507.2
N17529223: length 4.4
  BOTTOM w0.178: Q507.3 Q506.1 175.21,8.09 R758.1
N17529899: length 4.9
  TOP w0.178: J67.1 v1(177.91,3.38)
  BOTTOM w0.178: v1(177.91,3.38) 176.33,3.38 176.15,3.2 ; 176.15,3.2 C699.2 ; 176.15,3.2 Q506.3
N17530429: length 5.3
  TOP w0.178: R16.1 190.9,93.34 192.04,92.2 v1(192.46,92.2)
  BOTTOM w0.178: Q502.2 C540.1 192.46,93.34 v1(192.46,92.2)
N17530493: length 8.7
  TOP w0.178: R15.1 190.94,96.95 v1(191.88,96.95)
  BOTTOM w0.178: Q502.3 188.14,93.4 188.02,93.4 187.64,93.77 187.64,94.3 188.02,94.68 188.03,94.68 188.48,94.68 188.96,95.16 188.96,95.17 189.24,95.44 189.24,95.87 Q501.2 v1(191.88,96.95)
N17530807: length 1.4
  BOTTOM w0.178: R573.1 Q501.3
N17554994: length 2.7
  BOTTOM w0.178: R518.1 174.29,111.75 U501.12
N17554995: length 3.4
  BOTTOM w0.178: R513.2 171.59,115.8 173.41,115.8 173.64,115.57 U501.13
N173644741: length 1.1
  BOTTOM w0.178: R574.1 177.15,95 C542.2

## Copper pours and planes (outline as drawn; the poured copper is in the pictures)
AGND on LY5PWR: 13.65,95.25 20,95.25 20.64,95.89 21.75,95.89 26.35,91.28 26.35,90.12 27.9,88.57 32.07,88.57 32.07,85.57 34.61,85.57 34.61,89.53 41.21,89.53 41.21,92.08 37.86,95.43 30.16,95.43 30.16,93.34 31.18,93.34 31.18,91.31 28.39,91.31 28.26,91.44 28.26,92.71 21.91,99.06 16.83,99.06 16.83,100.56 13.65,100.56
GND on TOP (solid shape): 162.43,58.29 157.35,58.29 157.35,63.37 162.43,63.37
GND on TOP (solid shape): 163.7,111 158.62,111 158.62,116.08 163.7,116.08
GND on TOP (solid shape): 186.69,12.38 184.15,12.38 184.15,14.92 186.69,14.92
GND on TOP (solid shape): 191.3,48.82 187.3,48.82 187.3,52.32 191.3,52.32
GND on TOP (solid shape): 195.3,44.32 191.3,44.32 191.3,48.32 195.3,48.32
GND on BOTTOM (solid shape): 191.3,48.82 187.3,48.82 187.3,52.32 191.3,52.32
GND on BOTTOM (solid shape): 195.3,44.32 191.3,44.32 191.3,48.32 195.3,48.32
GND on BOTTOM (solid shape): 166.57,44.32 166.61,44.31 166.62,44.27 166.62,41.07 166.61,41.04 166.57,41.02 162.18,41.02 162.05,41.15 162.05,43.56 162.81,44.32
GND on LY2GND (solid shape): 197.14,7.46 199.12,6.53 199.13,6.51 199.14,6.49 199.14,5.59 199.77,4.95 199.77,1.4 198.63,0.25 194.69,0.25 194.18,0.76 193.6,0.76 193.58,0.77 193.56,0.78 193.13,1.34 192.8,1.97 192.72,2.17 192.66,2.37 192.62,2.46 192.63,2.47 192.91,5.28 194.97,7.2
GND on LY2GND (solid shape): 5.28,7.09 7.2,5.03 7.44,2.79 6.44,0.78 6.42,0.77 6.4,0.76 5.97,0.76 5.46,0.25 1.52,0.25 0.25,1.52 0.25,5.08 0.76,5.59 0.76,6.4 0.77,6.42 0.78,6.44 1.34,6.87 1.97,7.2 2.17,7.28 2.37,7.34 2.46,7.38 2.47,7.37
GND on LY2GND (solid shape): 7.44,119.29 0.78,117.06 0.77,117.08 0.76,117.1 0.76,117.73 0.25,118.24 0.25,121.54 0.76,122.05 0.76,122.9 0.77,122.92 0.78,122.94 1.34,123.37 1.97,123.7
GND on LY2GND (solid shape): 27.81,132.08 28.67,132.08 28.69,132.08 28.71,132.06 27.7,126.07 21.92,127.97 21.85,128.17 21.78,128.37 21.75,128.46 21.75,128.47 21.71,130.36 22.55,132.06 22.56,132.08 22.58,132.08 23.24,132.08 23.88,132.72 27.18,132.72
GND on LY2GND (solid shape): 134.87,132.08 135.67,132.08 135.69,132.08 135.71,132.06 134.7,126.07 128.92,127.97 128.85,128.17 128.78,128.37 128.75,128.46 128.75,128.47 128.71,130.36 129.55,132.06 129.56,132.08 129.58,132.08 130.3,132.08 130.94,132.72 134.24,132.72
GND on LY2GND (solid shape): 197.14,131.46 199.12,130.53 199.13,130.51 199.14,130.49 199.14,129.67 199.77,129.03 199.77,125.86 199.14,125.22 199.14,124.51 199.13,124.49 199.12,124.47 195.58,123.6 192.8,125.97 192.72,126.17 192.66,126.37 192.62,126.46 192.63,126.47 192.91,129.28 194.97,131.2
GND on BOTTOM: 84.07,83.44 84.23,73.79 87.12,73.79 87.12,66.17 101.98,66.16 101.98,73.03 101.35,73.03 101.35,74.42 101.98,74.42 101.98,83.82 100.97,83.82 100.97,84.45 92.71,84.45 92.71,83.44
GND on BOTTOM: 143.13,60.07 143.13,57.66 143.26,57.53 146.3,57.53 146.43,57.4 146.43,54.74 148.08,54.74 148.08,56.64 147.96,56.77 149.1,56.77 149.22,56.64 149.61,56.64 149.61,60.2 148.72,61.09 144.15,61.09
GND on LY2GND: 0.76,0.76 199.24,0.76 199.24,132.23 0.76,132.23
P12V on LY3: 89.53,28.57 92.71,28.57 93.34,27.94 93.34,20.32 90.81,17.78 87.63,17.78 87.63,19.68 88.27,20.32 88.9,20.32 88.9,27.94
P12V on LY5PWR: 153.35,64.14 153.35,60.33 155.57,60.33 155.57,54.61 164.15,54.61 168.59,59.05 168.59,123.83 184.47,123.83 184.47,130.81 161.89,130.81 136.32,105.24 136.32,101.6 156.53,101.6 156.53,67.31
P12V_IN on TOP (solid shape): 189.3,44.32 185.3,44.32 185.3,48.32 189.3,48.32
P12V_IN on BOTTOM (solid shape): 189.3,44.32 185.3,44.32 185.3,48.32 189.3,48.32
(no net) on TOP: 164.72,116.08 164.72,115.7 171.83,115.7 175.01,118.87 175.01,122.43 169.16,122.43 169.16,118.75 166.5,116.08
(no net) on TOP: 159.38,40.39 159.38,35.81 162.43,35.81 162.43,40.39
(no net) on TOP: 161.42,57.28 160.91,57.28 160.91,44.07 163.32,41.66 171.7,41.66 171.7,48.13 166.88,48.13 161.42,53.59
(no net) on TOP: 148.34,50.04 145.29,50.04 145.29,42.04 142.24,42.04 142.24,38.48 149.48,38.48 151,40.01 151,49.91 153.16,52.07 156.97,52.07 159.38,54.48 159.38,57.28 158.88,57.28 158.88,55.37 158.62,55.12 153.42,55.12
(no net) on TOP: 160.66,93.09 160.66,90.7 159.68,89.73 159.68,89.71 158.64,89.71 157.92,89 157.92,87.5 162.69,87.5 163.7,88.52 163.7,93.09
(no net) on TOP: 156.84,72.52 156.84,66.42 157.35,65.91 157.35,64.39 156.46,64.39 156.46,65.66 155.07,67.06 155.07,68.2 152.78,70.48 144.26,70.48 144.27,74.8 146.81,74.8 146.81,78.36 151,78.36
(no net) on TOP: 163.45,62.74 163.45,62.36 165.86,62.36 166.62,61.59 166.62,53.85 173.74,53.85 173.74,59.94 171.83,59.94 169.04,62.74
(no net) on TOP: 154.31,97.33 154.31,88.33 155.21,87.43 157.34,87.43 157.42,87.5 157.42,88.65 157.87,88.65 157.87,89.08 158.84,90.04 159.47,90.04 160.39,90.96 160.4,90.96 160.4,97.33
(no net) on TOP: 163.7,79.12 160.4,79.12 160.4,83.31 163.7,83.31
(no net) on TOP: 143.89,60.58 141.73,60.58 141.73,56.39 138.94,56.39 138.94,48.77 145.92,48.77 148.72,51.56 148.72,58.42 152.15,61.85 156.34,61.85 156.34,62.36 144.78,62.36 143.89,61.47
(no net) on TOP: 157.61,116.08 145.54,116.08 144.44,114.97 144.44,107.95 136.63,107.95 136.63,111.1 146.05,120.52 153.16,120.52 156.34,117.35 157.61,117.35
(no net) on TOP: 163.45,63.37 163.45,62.99 170.56,62.99 173.74,66.17 173.74,69.72 167.89,69.72 167.89,66.04 165.23,63.37
(no net) on TOP: 157.35,65.91 157.35,64.39 158.38,64.39 158.38,69.1 163.45,74.17 163.45,78.49 157.43,78.49 157.43,65.84
(no net) on TOP: 153.03,42.55 153.03,35.94 159.13,35.94 159.13,42.55
(no net) on TOP: 145.16,113.28 144.69,113.28 144.69,107.2 138.53,107.2 138.53,101.47 147.19,101.47 149.99,104.27 149.99,111.12 153.42,114.55 157.61,114.55 157.61,115.06 146.05,115.06 145.16,114.17
(no net) on TOP: 156.34,63.37 145.92,63.37 145.4,63.89 145.4,70.36 149.35,70.36 155.07,64.64 156.34,64.64
(no net) on TOP: 160.78,57.28 159.89,57.28 159.89,54.61 156.97,51.69 154.18,51.69 154.18,43.05 160.4,43.05 160.4,53.47 160.78,53.85
(no net) on TOP: 164.72,115.44 164.72,115.06 167.13,115.06 167.89,114.3 167.89,106.55 175.01,106.55 175.01,112.65 173.1,112.65 170.31,115.44
(no net) on BOTTOM: 145.41,70.61 145.41,65.66 149.61,65.66 149.61,70.61
(no net) on BOTTOM: 147.07,77.85 150.75,77.85 150.75,80.9 147.07,80.9
(no net) on BOTTOM: 150.88,76.83 147.07,76.83 147.07,73.15 150.88,73.15
(no net) on BOTTOM: 166.62,44.32 162.81,44.32 162.05,43.56 162.05,41.15 162.18,41.02 166.62,41.02
(no net) on BOTTOM: 144.02,70.61 144.02,65.53 140.21,65.53 140.21,70.61
(no net) on BOTTOM: 167.77,44.83 162.31,44.83 162.31,48.64 167.64,48.64 167.77,48.51
DMDP3P3VA on LY3: 111.76,13.97 116.84,13.97 116.84,18.41 111.12,24.13 107.31,24.13 107.31,18.41
DMDP3P3VB on LY3: 76.58,34.16 78.87,34.16 78.87,30.99 77.98,30.1 77.98,28.45 78.23,28.19 78.23,26.54 76.2,26.54 76.2,33.78
P1P1V on TOP: 111.76,88.9 111.76,74.93 112.39,74.3 120.65,74.3 120.65,90.81 119.74,91.8 110.43,101.11 110.43,101.6 103.5,101.6 99.69,97.79 99.69,95.25 105.41,95.25
P1P1V on TOP: 131.57,51.05 133.35,51.05 134.24,51.94 137.03,51.94 137.03,55.75 133.99,55.75 133.6,55.37 133.6,53.98 131.57,53.98
P1P1V on TOP: 126.36,71.12 126.36,68.58 135.89,68.58 135.89,74.3 141.6,74.3 143.51,76.2 146.05,76.2 146.05,78.74 146.69,79.38 146.69,80.64 147.32,81.28 147.32,85.72 146.69,86.36 140.34,86.36 140.34,81.92 143.51,81.92 143.51,80.01 142.88,79.38 142.24,79.38 140.34,77.47 134.62,77.47 129.54,72.39 127.64,72.39
P1P1V on TOP: 85.15,84.71 102.17,84.71 102.17,67.69 85.15,67.69
P1P1V on BOTTOM: 126.87,70.87 126.87,68.45 135.51,68.45 136.91,69.85 136.91,76.33 132.33,76.33
P1P1V on BOTTOM: 99.5,77.98 99.5,76.83 99.63,76.83 99.63,75.31 110.43,75.31 112.2,77.09 121.35,77.09 123.25,75.18 126.81,75.18 126.81,77.47 123,81.28 103.06,81.28 103.06,79.12 102.43,78.49 102.43,78.11 102.3,77.98
P1P1V on BOTTOM: 130.81,56.9 133.1,56.9 133.1,59.18 133.35,59.18 133.35,60.71 132.97,61.09 132.97,61.21 129.67,61.21 129.67,58.04
P1P1V on BOTTOM: 129.79,55.63 129.79,53.72 131.7,53.72 132.08,53.34 132.08,51.05 133.35,51.05 134.11,51.82 139.06,51.82 139.06,53.34 149.48,53.34 150.37,54.23 151.26,54.23 151.26,55.37 150.5,55.37 149.86,56.01 149.1,56.01 149.1,56.9 147.83,56.9 147.83,54.61 137.79,54.61 136.65,55.75 134.24,55.75 134.24,54.48 133.73,54.48 132.59,55.63
P1P1V on LY3: 129.54,58.42 132.72,58.42 135.25,60.96 135.25,75.56 129.54,75.56
P1P1V on LY5PWR: 130.18,60.96 130.18,50.16 151.15,50.16 151.15,55.07 145.25,60.96
P1P1V on LY5PWR: 138.75,77.47 137.61,76.33 104.45,76.33 102.68,78.11 100.14,78.11 100.14,75.69 102.46,75.69 102.46,74.79 105.01,74.79 105.88,73.91 145.05,73.91 145.05,86.93 140.65,86.93 140.65,81.92 140.4,81.66 138.75,81.66
P1P8V on LY5PWR: 70.17,17.78 70.17,31.11 74.78,31.11 74.78,55.41 80.33,60.96 80.33,63.25 81.85,63.25 82.36,63.75 85.15,63.75 85.15,68.45 86.3,69.6 86.3,75.95 86.17,75.82 84.65,75.82 84.65,78.23 86.68,78.23 86.68,85.22 88.71,85.22 88.71,82.93 92.14,82.93 92.14,84.45 94.74,84.45 95,84.2 95,83.5 96.33,82.17 98.11,82.17 98.11,77.09 99.73,75.46 102.02,75.46 102.02,74.77 104.95,74.77 106.06,73.66 144.46,73.66 145.1,74.3 145.1,87 138.11,87 138.11,87.63 137.48,88.27 137.48,92.08 153.99,92.08 153.99,70.48 152.08,68.58 128.59,68.58 126.56,70.61 104.97,70.61 102.75,72.83 100.9,72.83 100.9,68.71 105.98,63.63 105.98,46.1 111.19,40.89 111.19,34.67 112.59,33.27 112.59,30.86 113.16,30.29 113.16,22.05 111.3,20.19 100.13,20.19 99.59,20.73 99.59,29.29 94.79,34.09 93.47,34.09 91.85,32.46 91.85,28.65 90.3,27.1 90.3,25.3 88.09,23.09 88.09,21.08 84.79,17.78
P2P5V on BOTTOM: 147.64,48.26 150.81,48.26 150.81,51.44 147.07,51.44 147.07,53.21 139.06,53.21 139.06,51.69 134.76,51.69 134.94,44.45 139.38,44.45 140.65,43.18 140.65,34.42 162.88,34.42 162.88,40.64 158.88,40.64 158.88,37.85 150.88,37.85 150.88,40.64 147.64,40.64
P2P5V_PMD2 on TOP (solid shape): 163.65,93.09 163.69,93.08 163.7,93.04 163.7,88.52 162.69,87.5 157.98,87.5 157.94,87.52 157.92,87.55 157.92,89 158.64,89.71 159.68,89.71 159.68,89.73 160.66,90.7 160.66,93.04 160.67,93.08 160.71,93.09
P2P5V_PMD2 on BOTTOM: 138.75,106.05 152.08,106.05 152.08,101.52 148.69,101.52 148.69,93.34 163.51,93.34 163.51,87.63 147.64,87.63 141.92,93.34 141.92,95.25 138.75,98.42
P3P3V on LY5PWR: outline of 94 points within 0.76,0.76 199.24,132.23
PMD1K2_FB_P2P5V on TOP (solid shape): 160.35,97.33 160.39,97.32 160.4,97.28 160.4,93.35 160.4,90.97 159.47,90.04 158.84,90.04 158.76,89.97 158.53,89.97 157.79,89.23 157.73,89.23 157.73,89.17 157.67,89.11 157.67,88.7 157.66,88.66 157.62,88.65 157.42,88.65 157.42,87.5 157.34,87.43 155.21,87.43 154.31,88.33 154.31,97.28 154.32,97.32 154.36,97.33
PMD1K2_FB_P2P5V on TOP: 162.43,109.98 163.45,109.98 163.45,108.33 163.96,107.82 165.86,107.82 165.99,107.7 165.99,93.22 160.15,93.22 160.15,98.42 160.91,99.19 160.91,104.65 162.43,106.17
PMD1K_FB_MOT1 on TOP (solid shape): 173.69,69.72 173.72,69.71 173.74,69.67 173.74,66.17 170.56,62.99 163.5,62.99 163.46,63.01 163.45,63.04 163.45,63.2 163.46,63.24 163.5,63.25 164.15,63.25 164.24,63.22 164.34,63.2 165.09,63.2 165.14,63.25 165.3,63.25 165.3,63.42 165.61,63.72 165.61,63.75 167.89,66.04 167.89,66.07 167.95,66.16 168.06,66.15 168.91,66.53 168.06,66.9 167.95,66.89 167.89,66.98 167.89,69.67 167.91,69.71 167.94,69.72
PMD1K_FB_MOT2 on TOP (solid shape): 174.96,122.43 174.99,122.41 175.01,122.38 175.01,118.87 171.83,115.7 170.22,115.7 170.12,115.76 170.15,115.87 169.81,116.76 169.48,115.87 169.5,115.76 169.41,115.7 164.77,115.7 164.73,115.71 164.72,115.75 164.72,115.91 164.73,115.94 164.77,115.96 165.42,115.96 165.51,115.92 165.61,115.91 166.36,115.91 166.41,115.96 166.57,115.96 166.57,116.12 166.88,116.43 166.88,116.46 169.16,118.75 169.16,119.84 169.18,119.87 169.21,119.89 169.46,119.89 169.46,121.92 169.21,121.92 169.18,121.93 169.16,121.97 169.16,122.38 169.18,122.41 169.21,122.43
PMD1K_FB_MOT2 on BOTTOM: 168.53,126.11 171.2,126.11 171.2,117.35 168.4,117.35 168.28,117.47 168.28,125.98 168.4,125.98
PMD1K_FB_P2P5V on BOTTOM: 154.43,42.55 158.5,42.55 158.62,42.42 158.62,38.1 154.56,38.1 154.43,38.23
PMD1K_FB_P3P3V on TOP (solid shape): outline of 302 points within 160.91,41.66 171.7,57.28
PMD1K_FB_P5V on TOP (solid shape): outline of 171 points within 144.26,64.39 157.1,78.36
SWNODE2_CORE on TOP (solid shape): 156.34,117.35 157.56,117.35 157.59,117.33 157.61,117.3 157.61,116.17 157.59,116.13 157.56,116.12 156.81,116.12 156.76,116.13 156.72,116.13 155.03,116.13 155.01,116.14 154.99,116.15 154.6,116.3 154.23,116.1 154.21,116.08 154.19,116.08 145.54,116.08 144.44,114.97 144.44,108 144.42,107.96 144.39,107.95 136.68,107.95 136.65,107.96 136.63,108 136.63,111.1 136.65,111.13 136.71,111.14 136.74,111.09 136.74,111.05 138.85,111.05 138.85,113.32 139.12,113.59 139.23,113.62 139.29,113.52 139.29,113.3 139.29,113.28 139.28,113.26 139.64,112.39 139.99,113.26 139.98,113.28 139.98,113.3 139.98,114.45 141.78,116.26 142.35,116.26 142.35,116.83 146.05,120.52 153.16,120.52
SWNODE2_P2P5V on TOP: 160.15,109.98 160.66,109.98 160.66,98.93 154.94,98.93 154.94,107.95 160.15,107.95
SWNODE_CORE on TOP (solid shape): outline of 102 points within 145.4,63.37 156.34,70.36
SWNODE_MOT on TOP (solid shape): 171.83,59.94 173.69,59.94 173.72,59.93 173.74,59.89 173.74,53.9 173.72,53.86 173.69,53.85 170.07,53.85 169.74,53.98 169.4,53.85 166.67,53.85 166.64,53.86 166.62,53.9 166.62,61.1 166.62,61.9 165.93,62.31 165.91,62.31 165.86,62.36 165.35,62.36 165.32,62.37 165.3,62.41 164.53,62.41 164.44,62.45 164.34,62.47 163.5,62.47 163.46,62.48 163.45,62.52 163.45,62.69 163.46,62.72 163.5,62.74 169.04,62.74
SWNODE_MOT2 on TOP (solid shape): outline of 237 points within 164.73,106.55 175.01,115.44
SWNODE_P2P5V on TOP (solid shape): outline of 253 points within 142.24,38.48 159.38,57.27
SWNODE_P3P3V on TOP (solid shape): 160.21,57.28 160.25,57.26 160.26,57.23 160.26,56.39 160.28,56.29 160.31,56.2 160.31,55.42 160.73,55.42 160.77,55.41 160.78,55.37 160.78,53.85 160.4,53.47 160.4,52.57 160.39,52.55 160.38,52.53 160.14,52.1 160.38,51.67 160.39,51.65 160.4,51.63 160.4,43.1 160.39,43.07 160.35,43.05 154.23,43.05 154.19,43.07 154.18,43.1 154.18,51.64 154.19,51.67 154.23,51.69 156.28,51.69 156.31,51.68 156.33,51.66 156.96,51.38 157.29,51.98 157.29,52 157.31,52.02 159.89,54.61 159.89,55.37 159.91,55.41 159.94,55.42 159.97,55.42 159.97,56.2 160.01,56.29 160.02,56.39 160.02,57.19 160.11,57.28
SWNODE_P5V on TOP (solid shape): 157.78,78.48 157.97,78.45 158.16,78.48 158.17,78.49 163.4,78.49 163.43,78.47 163.45,78.44 163.45,74.96 162.57,74.08 162.56,74.08 162.2,73.74 162.29,73.27 162.31,73.25 162.31,73.23 162.29,73.19 162.26,73.18 161.72,73.18 161.72,72.44 158.7,69.42 158.41,69.42 158.41,69.13 158.38,69.1 158.38,66.29 158.36,66.26 158.33,66.24 157.81,66.24 157.81,65.47 157.77,65.38 157.76,65.28 157.76,64.44 157.75,64.4 157.71,64.39 157.52,64.39 157.49,64.4 157.47,64.44 157.47,65.19 157.48,65.23 157.48,65.28 157.48,65.61 157.47,65.63 157.47,66.24 157.46,66.24 157.43,66.27 157.43,70.45 157.44,70.48 157.47,70.5 157.86,71 157.47,71.49 157.44,71.51 157.43,71.54 157.43,78.44 157.44,78.47 157.48,78.49 157.77,78.49
N16830232 on TOP (solid shape): outline of 387 points within 138.94,48.77 156.33,62.36
N16830232 on BOTTOM: 149.22,65.02 152.4,65.02 152.53,64.9 152.53,62.1 151.38,60.96 149.86,60.96 149.73,60.83 148.97,60.83 148.49,60.35 148.21,60.35 147.96,60.6 147.96,62.74 149.22,64.01
N17059579 on TOP (solid shape): outline of 185 points within 138.53,101.47 157.6,115.06

Small or netless copper shapes (teardrops, artwork), in the pictures only: 207 on TOP, 11 on BOTTOM

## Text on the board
BOTTOM: LAYER 6 - SECONDARY SIDE | 6    12
Ref Des/Assembly Bottom: ASSEMBLY - SECONDARY SIDE | 2     2
Board Geometry/Soldermask Bottom: SOLDERMASK - SECONDARY SIDE | 8    12
Ref Des/Silkscreen Bottom: FID4 | FID6 | FID5 | SILKSCREEN - SECONDARY SIDE | 10    12
TOP: LAYER 1 - PRIMARY SIDE | 1    12
Ref Des/Assembly Top: 2 | 1 | 119 | 120 | ASSEMBLY - PRIMARY SIDE | 1      2
Board Geometry/Soldermask Top: SOLDERMASK - PRIMARY SIDE | 7    12
